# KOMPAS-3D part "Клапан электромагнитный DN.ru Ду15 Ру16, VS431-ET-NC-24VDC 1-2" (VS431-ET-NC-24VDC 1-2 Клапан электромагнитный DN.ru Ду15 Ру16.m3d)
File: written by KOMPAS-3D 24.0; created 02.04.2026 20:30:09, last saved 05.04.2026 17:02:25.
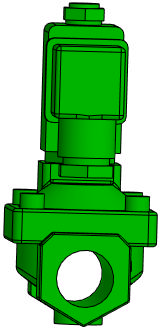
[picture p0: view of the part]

Document properties: Автор: artio; Полное имя файла: C:\Users\artio\OneDrive\Рабочий стол\Клапан электромагнитный DN.ru\VS431\VS431-ET-NC\VS431-ET-NC-24VDC\Ду15\VS431-ET-NC-24VDC 1-2 Клапан электромагнитный DN.ru Ду15 Ру16.m3d

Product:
- Body: Тело 1  | qty 1
    Масса: 1.030062
- Part/product: Клапан электромагнитный DN.ru Ду15 Ру16  | designation VS431-ET-NC-24VDC 1-2
    Масса: 0.732
    Раздел спецификации: Прочие изделия
    Примечание: D130-04740
    additional columns: ef56311e-7521-43dc-8291-0e6108b3d81d; VS400-ET-NC-220VAC 1-2; artio; c; Шероховатость не задана; Да

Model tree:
1. Операция без истории:1

Expressions: VS431-ET-NC-24VDC 1-2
